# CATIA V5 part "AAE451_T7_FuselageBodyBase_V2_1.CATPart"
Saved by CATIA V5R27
Part number: FB1
Bounding box of the stored display mesh (mm): x -98.442 to 98.442, y -250 to -100, z -67 to 0
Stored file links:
  W:\AAE 451\AAE451_T7_FuselageAssemble_V2\AAE451_T7_FuselageBodyBase_V2_1.CATPart
  W:\AAE 451\AAE451_T7_FuselageBody.CATPart
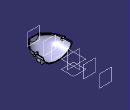
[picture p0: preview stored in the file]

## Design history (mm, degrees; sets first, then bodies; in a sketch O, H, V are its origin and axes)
Body1 (main body)
Body2
  Plane1: type Offset, RefPlane zx-plane, Offset 250, reversed
  Plane2: type Offset, RefPlane zx-plane, Offset 100
  Sketch1 on Plane1, origin (0, -250, 0), H (-1, 0, 0), V (0, 0, 1)
    circle A1 centre (0, 0) radius 30
    distance O A1 = 30
  Plane3: type Offset, RefPlane zx-plane, Offset 150, reversed
  Sketch2 on Plane2, origin (0, 100, 0), H (-1, 0, 0), V (0, 0, 1)
    construction line L1 (0, 60) -> (0, -40)
    point P1 (0, 60)
    construction line L2 (-92.2886, 30) -> (87.7114, 30)
    point P5 (0, 30)
    coincidence: P1 V, P5 L2, P5 L1
    vertical: L1 V
    horizontal: L2 H
  Sketch3 on Plane2, origin (0, 100, 0), H (-1, 0, 0), V (0, 0, 1)
    construction line L1 (0, -100) -> (0, 70)
    point P1 (0, -100)
    construction line L2 (-103.4986, 30) -> (116.5014, 30)
    point P5 (0, 30)
    point P6 (0, 60)
    construction line L3 (-60, 60) -> (60, 60)
    point P7 (-60, 60)
    reference projected curve E1 from Sketch4.E1
    ellipse A1 centre (0, 60) semi-axes 60, 35 rotation 180 from (-60, 60) to (60, 60)
    point P8 (-60, 60)
    point P9 (60, 60)
    point P10 (60, 60)
    point P11 (-60, 60)
    ellipse A2 centre (0, 60) semi-axes 60, 35 rotation 180 from (-60, 60) to (60, 60)
    "Radius" A1 = 60
    "Radius" A1 = 35
    coincidence: P1 V, P5 L2, P5 L1, P6 L1, A1 P7, P7 L3, P6 L3
    vertical: L1 V
    horizontal: L2 H, L3 H, A1 H
    tangency: L3 E1
    symmetry: P9 P10 L3, P8 P11 L3, A1 A2 L3
  Sketch4 on zx-plane, origin (0, 0, 0), H (-1, 0, 0), V (0, 0, 1)
    projected curve E1 from Sketch5.A1
  Sketch5 on Plane3, origin (0, -150, 0), H (-1, 0, 0), V (0, 0, 1)
    construction line L1 (50, 50) -> (50, -50)
    construction line L2 (50, -50) -> (-50, -50)
    construction line L3 (-50, -50) -> (-50, 50)
    construction line L4 (-50, 50) -> (50, 50)
    point P1 (50, 50)
    point P2 (50, -50)
    point P3 (-50, -50)
    point P4 (-50, 50)
    construction line L5 (0, -60) -> (0, 90)
    point P5 (0, -60)
    construction line L6 (-100, 0) -> (110, 0)
    point P7 (-100, 0)
    ellipse A1 centre (0, 0) semi-axes 90.4534, 60 rotation 0
    point P9 (0, 60)
    length L1 = 100
    length L4 = 100
    vertical: L1 V, L3 V, L5 V
    horizontal: L2 H, L4 H, L6 H, A1 H
    equidistance: L1 L3 O, L2 L4 O
    coincidence: P5 V, P7 H, P9 L5, A1 P9, P2 A1, A1 P3, P1 A1, P4 A1
    parallelism: A1 L6
  Loft1: solid, Sections (Sketch3; Sketch4; Sketch5; Sketch1)
  Sketch6 on face of Loft1, origin (0, 100, 0), H (-1, 0, 0), V (0, 0, 1)
    line L1 (-70, 95) -> (70, 95)
    line L2 (70, 95) -> (70, 60)
    line L3 (70, 60) -> (-70, 60)
    line L4 (-70, 60) -> (-70, 95)
    reference projected curve E1 from edge [face of Loft1 | face of Loft1]
    construction line L5 (-60, 60) -> (60, 60)
    length L1 = 140
    horizontal: L1 H, L3 H, L5 H
    vertical: L2 V, L4 V
    coincidence: L3 L5
    tangency: L1 E1
    symmetry: L4 L2 V
  Pocket1: profile Sketch6, direction (0, -1, 0), through (limit type 6)
  Plane4: type Offset, RefPlane Plane2, Offset 100
  Sketch7 on Plane4, origin (0, 200, 0), H (-1, 0, 0), V (0, 0, 1)
    projected line E2 (-60, 60) -> (60, 60) from edge [face of Loft1 | face of Pocket1 from Sketch6.L3]
  Pad1: profile Sketch7, direction (0, 1, 0), up to the existing solid (limit type 3)
  Sketch8 on face of Loft1, origin (0, -250, 0), H (1, 0, 0), V (0, 0, 1)
    line L1 (-97.5192, 0) -> (97.5192, 0)
    point P1 (-97.5192, 0)
    point P2 (97.5192, 0)
    projected line E1 (-62.8781, 60) -> (63.056, 60) from edge [face of Loft1 | face of Pad1]
    line L2 (-97.5192, 0) -> (-62.8781, 60)
    line L3 (97.5192, 0) -> (63.056, 60)
    angle L1 L2 = 60
    horizontal: L1 H
    symmetry: P1 P2 V
    coincidence: H L1
  Pocket2: profile Sketch8, direction (0, 1, 0), through (limit type 3)
  Shell1: ExtOffset 0, Face face of Pocket2 from Sketch8.L1, IntOffset 4
  Sketch9 on face of Pocket2 from Sketch8.L1, origin (0, 0, 0), H (1, 0, 0), V (0, 1, 0)
    arc A1 centre (93.4423, -150) radius 5 from (93.4423, -155) to (93.4423, -145) ccw
    point P1 (93.4423, -150)
    line L1 (93.4423, -145) -> (86.4534, -145)
    point P2 (86.4534, -145)
    line L2 (93.4423, -155) -> (86.4312, -155)
    point P3 (86.4312, -155)
    reference projected curve E1 from edge [face of Pocket2 from Sketch8.L1 | face of Shell1]
    reference projected curve E2 from edge [face of Shell1 | face of Pocket2 from Sketch8.L1]
    reference intersected line E3 through (0, -150) direction (-1, 0) from Plane3
    line L3 (86.4534, -145) -> (86.4312, -155)
    distance L1 L2 = 10
    distance L3 P1 = 7
    horizontal: L1 H, L2 H
    tangency: L1 A1, L2 A1
    coincidence: P3 E1, P2 E2, E3 P1
  Pad2: profile Sketch9, direction (0, 0, -1), length 10
  RectPattern1: of Pad2, direction 1 instances 3, spacing 75, along yz-plane
  Mirror1: of RectPattern1, about yz-plane
  Plane5: type Offset, RefPlane xy-plane, Offset 55, reversed
  Sketch10 on Plane5, origin (0, 0, -55), H (1, 0, 0), V (0, 1, 0)
    line L1 (67.5, -137.75) -> (-67.5, -137.75)
    line L2 (-67.5, -137.75) -> (-67.5, -162.25)
    line L3 (-67.5, -162.25) -> (67.5, -162.25)
    line L4 (67.5, -162.25) -> (67.5, -137.75)
    construction line L5 (132.2933, -150) -> (-145.9619, -150)
    distance L4 L2 = 135
    length L2 = 24.5
    distance L5 H = 150
    horizontal: L1 H, L3 H
    vertical: L2 V, L4 V
    symmetry: L4 L2 V, L1 L3 L5
  Pad3: profile Sketch10, direction (0, 0, -1), length 12, opposite side up to the existing solid (limit type 2)
  Fillet1: radius 10, on edge [end face of Pad3 | face of Pad3 from Sketch10.L4]; edge [end face of Pad3 | face of Pad3 from Sketch10.L2]
  Sketch11 on face of RectPattern1, origin (0, 0, 0), H (1, 0, 0), V (0, 1, 0)
    circle A1 centre (93.4423, -150) radius 2.5
    reference projected arc E1 centre (93.4423, -150) radius 5 from (93.4423, -155) to (93.4423, -145) ccw from edge [face of Pad2 from Sketch9.A1 | face of RectPattern1]
    radius A1 = 2.5
    concentricity: A1 E1
  Pocket3: profile Sketch11, direction (0, 0, -1), through (limit type 3)
  RectPattern2: of Pocket3, direction 1 instances 3, spacing 75, along yz-plane
  Mirror2: of RectPattern2, about yz-plane
  Plane6 "PRINT CAPACITY": type Offset, RefPlane Plane1, Offset 150
  Sketch12 on Plane6, origin (0, -100, 0), H (-1, 0, 0), V (0, 0, 1)
    point P1 (-2.7383, -33.5)
    line L1 (146.5133, 0) -> (146.5133, -67)
    line L2 (146.5133, -67) -> (-151.9899, -67)
    line L3 (-151.9899, -67) -> (-151.9899, 0)
    line L4 (-151.9899, 0) -> (146.5133, 0)
    reference projected line E1 (-67.5, -67) -> (67.5, -67) from edge [end face of Pad3 | face of Pad3 from Sketch10.L1]
    vertical: L1 V, L3 V
    horizontal: L2 H, L4 H
    equidistance: L1 L3 P1, L2 L4 P1
    coincidence: L4 H, L2 E1
  Pocket4: profile Sketch12, direction (0, 1, 0), through (limit type 3)
  Sketch13 on end face of Pad3, origin (0, 0, -67), H (1, 0, 0), V (0, -1, 0)
    circle A1 centre (-37, 150) radius 2.972
    point P1 (-37, 150)
    reference projected line E1 (-67.5, 162.25) -> (67.5, 162.25) from edge [end face of Pad3 | face of Pad3 from Sketch10.L3]
    reference projected line E2 (67.5, 137.75) -> (-67.5, 137.75) from edge [end face of Pad3 | face of Pad3 from Sketch10.L1]
    circle A2 centre (37, 150) radius 2.972
    radius A1 = 2.972
    distance P1 V = 37
    equidistance: E1 E2 P1
    symmetry: A1 A2 V
  Pocket5: profile Sketch13, direction (0, 0, 1), length 7.79
  Sketch14 on face of RectPattern1, origin (0, 0, 0), H (1, 0, 0), V (0, 1, 0)
    arc A1 centre (-76.4423, -150) radius 5 from (-76.4423, -155) to (-76.4423, -145) ccw
    point P1 (-76.4423, -150)
    line L1 (-86.4534, -145) -> (-76.4423, -145)
    point P2 (-86.4534, -145)
    line L2 (-86.4312, -155) -> (-76.4423, -155)
    point P3 (-86.4312, -155)
    reference projected line E1 (-86.4534, -145) -> (-86.4312, -155) from edge [face of RectPattern1 | face of Mirror1]
    reference projected line E2 (-86.4534, -145) -> (-86.4312, -155) from edge [face of RectPattern1 | face of Mirror1]
    line L3 (-86.4312, -155) -> (-86.4534, -145)
    construction line L4 (-93.4423, -150) -> (-76.4423, -150)
    point P4 (-93.4423, -150)
    reference projected circle E3 centre (-93.4423, -150) radius 2.5 from edge [face of Mirror2 | face of RectPattern1]
    radius A1 = 5
    distance P1 L3 = 10
    horizontal: L1 H, L2 H, L4 H
    coincidence: P3 E1, P2 E2
    concentricity: P4 E3
    tangency: L1 A1, L2 A1
  Pad4: profile Sketch14, direction (0, 0, -1), length 10
  Sketch15 on face of Pad4, origin (-76.5818, -149.4637, 0), H (1, 0, 0), V (0, 1, 0)
    point P1 (0.1395, -0.5363)
    reference projected arc E1 centre (0.1395, -0.5363) radius 5 from (0.1395, -5.5363) to (0.1395, 4.4637) ccw from edge [face of Pad4 from Sketch14.A1 | start face of Pad4]
    concentricity: P1 E1
  Hole1: placed by Sketch15, at (-76.4423, -150, 0) direction (0, 0, -1), diameter 5.944, depth 8.9, V-bottom angle 120, countersink depth 7.9, countersink angle 8
  Mirror3: of Pad4, Hole1, about yz-plane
